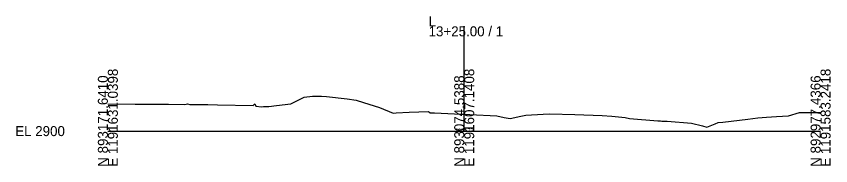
# Model space of a CAD drawing. Extents: x -26 to 203, y -10 to 7027.
# Drawn here: x -25.7 to 202.8, y 6490.3 to 6532.2 of the extents above; entities that cross this region are included whole.
import ezdxf

# ---------------------------------------------------------------- set-up
doc = ezdxf.new("R2010")
doc.units = 0
for name, color, linetype in [('Default', 7, 'Continuous'), ('Exist Cross Section Cell', 7, 'Continuous'), ('Prop CMT Pvmt Course 3 Wedge', 7, 'Continuous'), ('Scratch_Level_6', 7, 'Continuous')]:
    doc.layers.add(name, color=color, linetype=linetype)

msp = doc.modelspace()

# ---------------------------------------------------------------- linework, layer by layer
at = {"layer": 'Exist Cross Section Cell'}
for p, q in [((100, 6500), (100, 6529.36)), ((0, 6500), (100, 6500)), ((100, 6500), (200, 6500))]:
    msp.add_line(p, q, dxfattribs=at)
at = {"layer": 'Prop CMT Pvmt Course 3 Wedge'}
for p, q in [((51.36, 6507.6), (55.05, 6509.54)), ((55.05, 6509.54), (57.45, 6509.79)), ((57.45, 6509.79), (59.94, 6509.75)), ((59.94, 6509.75), (61.36, 6509.66)), ((61.36, 6509.66), (67.18, 6509)), ((67.18, 6509), (69.72, 6508.71)), ((69.72, 6508.71), (71.71, 6507.99)), ((0, 6507.62), (7.71, 6507.59)), ((7.71, 6507.59), (8.34, 6507.59)), ((8.34, 6507.59), (8.95, 6507.58)), ((8.95, 6507.58), (16.36, 6507.52)), ((16.36, 6507.52), (17, 6507.53)), ((17, 6507.53), (21.63, 6507.49)), ((21.63, 6507.49), (22.31, 6507.63)), ((22.31, 6507.63), (23.05, 6507.48)), ((23.05, 6507.48), (24.05, 6507.48)), ((24.05, 6507.48), (24.63, 6507.49)), ((24.63, 6507.49), (26.44, 6507.46)), ((26.44, 6507.46), (28.04, 6507.42)), ((28.04, 6507.42), (30.74, 6507.38)), ((30.74, 6507.38), (40.8, 6507.16)), ((40.8, 6507.16), (41.2, 6507.6)), ((41.2, 6507.6), (41.54, 6507.02)), ((41.54, 6507.02), (43.14, 6506.84)), ((43.14, 6506.84), (43.66, 6506.86)), ((43.66, 6506.86), (45.13, 6506.85)), ((45.13, 6506.85), (47.3, 6507.13)), ((47.3, 6507.13), (51.36, 6507.6)), ((71.71, 6507.99), (76.22, 6506.61)), ((76.22, 6506.61), (80.02, 6505.07)), ((80.02, 6505.07), (80.89, 6505.11)), ((80.89, 6505.11), (84.57, 6505.28)), ((84.57, 6505.28), (89.96, 6505.48)), ((89.96, 6505.48), (90.43, 6505.14)), ((90.43, 6505.14), (90.75, 6505.13)), ((90.75, 6505.13), (91.66, 6505.11)), ((91.66, 6505.11), (99.13, 6504.76)), ((99.13, 6504.76), (100.27, 6504.71)), ((100.27, 6504.71), (101.56, 6504.64)), ((101.56, 6504.64), (109.13, 6504.26)), ((109.13, 6504.26), (111.21, 6503.83)), ((112.93, 6503.55), (115.93, 6504.14)), ((115.93, 6504.14), (117.28, 6504.42)), ((117.28, 6504.42), (122.13, 6504.73)), ((122.13, 6504.73), (124.03, 6504.85)), ((124.03, 6504.85), (131.01, 6504.61)), ((131.01, 6504.61), (138.69, 6504.4)), ((138.69, 6504.4), (141.46, 6504.15)), ((141.46, 6504.15), (145.12, 6503.8)), ((184.78, 6503.88), (187.63, 6504.11)), ((187.63, 6504.11), (191.02, 6504.24)), ((191.02, 6504.24), (194.07, 6505.19)), ((194.07, 6505.19), (200, 6505.23)), ((111.21, 6503.83), (112.93, 6503.55)), ((145.12, 6503.8), (146.42, 6503.5)), ((146.42, 6503.5), (154.37, 6502.89)), ((154.37, 6502.89), (155.08, 6502.88)), ((155.08, 6502.88), (155.49, 6502.82)), ((155.49, 6502.82), (156.91, 6502.74)), ((156.91, 6502.74), (163.82, 6502.22)), ((163.82, 6502.22), (166.83, 6501.49)), ((168.12, 6501.12), (170.4, 6502.04)), ((170.4, 6502.04), (171.29, 6502.39)), ((171.29, 6502.39), (172.55, 6502.47)), ((172.55, 6502.47), (179.59, 6503.3)), ((179.59, 6503.3), (182.35, 6503.67)), ((182.35, 6503.67), (184.78, 6503.88)), ((166.83, 6501.49), (168.12, 6501.12))]:
    msp.add_line(p, q, dxfattribs=at)

# ---------------------------------------------------------------- texts
at = {"layer": 'Default'}
msp.add_text('-', height=0.0001, dxfattribs=at).set_placement((0, 6500))
at = {"layer": 'Exist Cross Section Cell'}
for s, p in [('L', (90, 6529.36)), ('13+25.00 / 1', (90, 6526.56)), ('EL 2900', (-26, 6498.6))]:
    msp.add_text(s, height=2.8, dxfattribs=at).set_placement(p)
for s, p in [('E 1191631.0398', (2.8, 6490)), ('E 1191607.1408', (102.8, 6490)), ('E 1191583.2418', (202.8, 6490)), ('N 893171.6410', (0, 6490)), ('N 893074.5388', (100, 6490)), ('N 892977.4366', (200, 6490))]:
    msp.add_text(s, height=2.8, rotation=90, dxfattribs=at).set_placement(p)
at = {"layer": 'Scratch_Level_6'}
msp.add_text('2904.72', height=1, dxfattribs=at).set_placement((97.51, 6499.72))

doc.saveas('drawing.dxf')
